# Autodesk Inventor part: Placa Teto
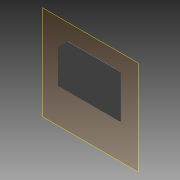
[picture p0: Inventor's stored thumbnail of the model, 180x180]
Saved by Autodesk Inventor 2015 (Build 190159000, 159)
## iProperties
Created: 2015-04
Part Number: Placa Teto
Material: Generic
Document SubType Name: Modeling
Designer: suporte
Density: 1 g/cm^3
Appearance: Default
Author: suporte
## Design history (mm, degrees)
workplane "Work Plane1"
sketch "Sketch1"
  geometry: L1 (-662.5, -250)-(-662.5, 456.396); L2 (-662.5, 456.396)-(-468.761, 650); L3 (-468.761, 650)-(637.5, 650); L4 (637.5, 650)-(637.5, -250); L5 (637.5, -250)-(-662.5, -250); L6 (-812.5, 518.558)-(-812.5, -400) reference; L7 (-530.862, 800)-(-812.5, 518.558) reference; L8 (87.5, -400)-(-812.5, -400) reference; L9 (787.5, -900)-(787.5, 900) reference; 1 further point
  constraints: 10 end point, 2 perpendicular, 1 horizontal, 1 parallel, 1 vertical
  dimensions: "d0" = 900 distance of L3.end L4.end; "d1" = 1300 distance of L4.end L1.start; "d2" = 150 distance between parallel lines of L9 L4; "d3" = 150 distance between parallel lines of L8 L5; "d4" = 150 distance between parallel lines of L7 L2
extrude "Extrusion1" new body sketch "Sketch1" distance "d5" = 12.5; taper "d6" = 0 deg
sketch "Sketch2"
  geometry: L1 (2.219, -12.5)-(1, -12.5); L2 (1300, -12.5)-(0, -12.5) reference; L3 (3, -12.5)-(1, -12.5); A1 r 1 centre (2, -12.5) between (3, -12.5) and (1, -12.5); 1 further point
  constraints: 4 end point, 3 point on line, 2 horizontal, 2 point on circle, 1 centre point
  dimensions: "d7" = 1 radius of A1; "d8" = 2 distance of A1.centre L2.end
extrude "Extrusion2" cut sketch "Sketch2" stored distance "d9" = 12.5; taper "d10" = 0 deg
fillet "Fillet1" dims "d14" = 2, "d15" = 2
body "Solid1"
pattern_linear "Rectangular Pattern2"
node "Reference1"
node "Reference2"
node "Reference3"
node "Reference4"
